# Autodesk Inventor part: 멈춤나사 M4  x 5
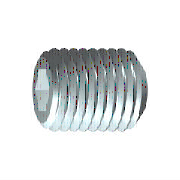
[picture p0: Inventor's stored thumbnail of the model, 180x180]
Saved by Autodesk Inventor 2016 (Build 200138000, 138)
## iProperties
IsCustomPart: 1
Created: 2012-02
Part Number: 멈춤나사 M4  x 5
Material: 강철, 연강
Description: 6각 소켓 머리 없는 멈춤 나사
Document SubType Name: Modeling
Standard: KS B 1028
Designer: mduedu
Standards Organization: KS
Language: ko-KR
Size Designation: 납작점M4x5
Categories: <MemberInstance><Categories><Category DisplayName="조임쇠" InternalName="e4da775c-781d-43d5-af7c-5136215cf5a6" Mnemonic="FSTN"><Category DisplayName="볼트" InternalN
Density: 7.85 g/cm^3
Appearance: 노란색
Mass: 0.69719 g
Surface Area: 1.37125 cm^2
Volume: 0.088814 cm^3
Author: mduedu
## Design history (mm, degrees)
sketch "스케치1"
  geometry: L1 (0, 0)-(4.833, 0); L2 (8, 1.155)-(8, 2); L3 (8, 2)-(0, 2); L4 (8, 1.155)-(5.5, 1.155); L5 (5.5, 1.155)-(4.833, 0); L6 (0, -0.4)-(0, 2.4) reference; L7 (0, 2)-(0, 0)
  constraints: 13 end point, 3 parallel, 1 collinear, 1 perpendicular, 1 point on line
  dimensions: "d0" = 2.5 distance of L2.start L4.end (= INTI); "d1" = 60 deg angle of L5 L1; "d2" = 4 diameter of L3 L1 (= NND); "d3" = 2.3094 diameter of L4 L1 (= 1.1547 x SW); "d5" = 8 distance from line of L2 L3.end (= NLG)
revolve "본체" sketch "스케치1" stored, may be unused: angle "d6" = 90 deg
sketch "스케치2"
  geometry: L1 (-0.577, 1)-(0.577, 1); L2 (0.577, 1)-(1.155, 0); L3 (1.155, 0)-(0.577, -1); L4 (0.577, -1)-(-0.577, -1); L5 (-0.577, -1)-(-1.155, 0); L6 (-1.155, 0)-(-0.577, 1); A1 r 1.155 centre (0, 0) between (-0.577, 1) and (0.577, 1) reference; 2 further points
  constraints: 12 end point, 2 point on circle, 1 coincident, 1 horizontal, 11 other
extrude "슬롯" join sketch "스케치2" taper "d9" = 0 deg; stored distance "d21" = 10
workaxis "Work Axis1"
workplane "Work Plane1"
body "Solid1"
chamfer "모따기1" distance "d7" = 0.42941 (= -0.5 x GD1 + 0.5 x NND); stored, may be unused: angle "d8" = 45 deg (= FAWI), second distance "d29" = 0.42941 (= -0.5 x GD1 + 0.5 x NND)
feature "스레드" dims "d11" = 8 (= NLG), "d12" = 0
chamfer "모따기2" distance "d13" = 0.42941 (= -0.5 x GD1 + 0.5 x NND); stored, may be unused: angle "d14" = 45 deg (= FAWI), second distance "d30" = 0.42941 (= -0.5 x GD1 + 0.5 x NND)
other parameters: "NND" = 4 [user parameter; used in 5 equation terms], "NLG" = 8 [user parameter; used in 2 equation terms], "INTI" = 2.5 [user parameter; used in 1 equation term], "FAWI" = 45 deg [user parameter; used in 2 equation terms], "SW" = 2 [user parameter; used in 2 equation terms], "GD1" = 3.14117 (= THREADDIA - 1.2269 x PTC) [user parameter; used in 4 equation terms], "d4" = 0, "FAWI1" = 45 deg [user parameter], "d15" = 0, "d31" = 0, "GUL" = 0.42941 (= 0.61345 x PTC) [user parameter], "SPD" = 2.5 [user parameter], "TPU" = 14.28571 (computed from PTC) [user parameter], "TOA" = 30 deg [user parameter], "THREADDIA" = 4 [user parameter; used in 1 equation term], "PTC" = 0.7 [user parameter; used in 4 equation terms], "GAL" = 0.42941 (= 0.61345 x PTC) [user parameter], "E0" = 2.31 (= 1.155 x SW) [user parameter]
